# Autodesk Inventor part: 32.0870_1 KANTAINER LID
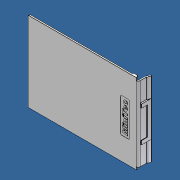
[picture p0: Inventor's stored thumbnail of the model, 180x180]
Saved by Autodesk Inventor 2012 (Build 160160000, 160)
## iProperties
Created: 2013-07
Part Number: 32.0870_1 KANTAINER LID
Material: Polycarbonate, Clear
Document SubType Name: Modeling
Designer: Admin
Density: 1.2 g/cm^3
Mass: 52.8979 g
Surface Area: 455.332 cm^2
Volume: 44.0816 cm^3
Author: Admin
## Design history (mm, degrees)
node "001049361"
node "Volumenkörper1"
node "Base1"
